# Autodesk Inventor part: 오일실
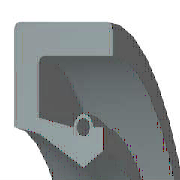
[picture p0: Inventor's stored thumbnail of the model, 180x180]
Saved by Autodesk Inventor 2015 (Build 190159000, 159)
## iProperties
IsCustomPart: 1
Created: 2015-10
Part Number: 오일실
Material: Rubber
Description: 오일-실
Document SubType Name: Modeling
Standard: KS B 2804
Designer: mdu
Standards Organization: KS
Language: ko-KR
Size Designation: S - 25 38 8
Categories: <MemberInstance><Categories><Category DisplayName="샤프트 부품" InternalName="7f7aeb1f-a693-4053-b835-cee3144e0d98" Mnemonic="SHFT"><Category DisplayName="실링" Intern
Density: 0.93 g/cm^3
Appearance: Rubber - Black - Version 1.1
Mass: 2.23721 g
Surface Area: 37.0166 cm^2
Volume: 2.4056 cm^3
Author: mdu
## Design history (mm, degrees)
revolve "본체" stored, may be unused: angle "d17" = 90 deg
revolve "스프링1" stored, may be unused: angle "d18" = 90 deg
body "Solid1"
sketch "스케치1"
  geometry: L1 (0, 19)-(8, 19); L2 (8, 19)-(8, 17.75); L3 (8, 17.75)-(1.75, 17.75); L4 (0, 19)-(0, 14.6); L5 (0, 14.6)-(1.75, 14.25); L6 (1.75, 14.25)-(4.9, 12.5); L7 (4.9, 12.5)-(0, 12.5); L8 (6.3, 13.375)-(6.3, 14.6); L9 (0, 0)-(9.586, 0) reference; L10 (4.9, 12.5)-(6.3, 13.375); L11 (0, 18)-(0, -3) reference; L12 (-1.917, 0)-(11.503, 0) reference; L13 (4.2, 14.6)-(1.75, 15.09); L14 (1.75, 15.09)-(1.75, 17.75); L15 (6.3, 14.6)-(5.6, 14.6); C1 r 0.455 at (4.9, 14.6); A1 r 0.7 centre (4.9, 14.6) between (5.6, 14.6) and (4.2, 14.6)
  constraints: 26 end point, 5 horizontal alignment, 4 perpendicular, 2 centre point, 2 collinear, 2 horizontal, 2 parallel, 2 point on circle, 2 point on line, 2 vertical alignment, 1 coincident
  dimensions: "d0" = 38 diameter of L1 L9 (= SD2); "d1" = 26.75 diameter of L8.start L9 (= ABDM); "d2" = 1.25 distance of L1.end L2.end (computed from SD); "d3" = 0.91 diameter of C1 (= SPDI); "d4" = 1.4 diameter of A1 (= SPDA); "d5" = 25 diameter of L6.end L9 (= NND); "d6" = 28.5 diameter of L5.end L9 (= TKDM); "d7" = 29.2 diameter of L4.end L9 (= HLDM); "d8" = 4.9 distance from line of C1.centre L4 (= SPDST); "d9" = 6.3 distance between parallel lines of L8 L4 (= SDI); "d10" = 8 distance between parallel lines of L2 L4 (= SWDT); "d12" = 1.75 distance between parallel lines of L14 L4 (= SD)
fillet "모깎기1" dims "d11" = 0.3 (= RR)
other parameters: "SD2" = 38 [user parameter; used in 1 equation term], "SWDT" = 8 [user parameter; used in 1 equation term], "RR" = 0.3 [user parameter; used in 1 equation term], "SD" = 1.75 [user parameter; used in 2 equation terms], "NND" = 25 [user parameter; used in 1 equation term], "SPDA" = 1.4 [user parameter; used in 1 equation term], "SPDI" = 0.91 [user parameter; used in 1 equation term], "TKDM" = 28.5 [user parameter; used in 1 equation term], "HLDM" = 29.2 [user parameter; used in 1 equation term], "ABDM" = 26.75 [user parameter; used in 1 equation term], "SDI" = 6.3 [user parameter; used in 1 equation term], "SPDST" = 4.9 [user parameter; used in 1 equation term], "d13" = 0, "d14" = 0, "d15" = 0, "LAB" = 0.35 [user parameter]
